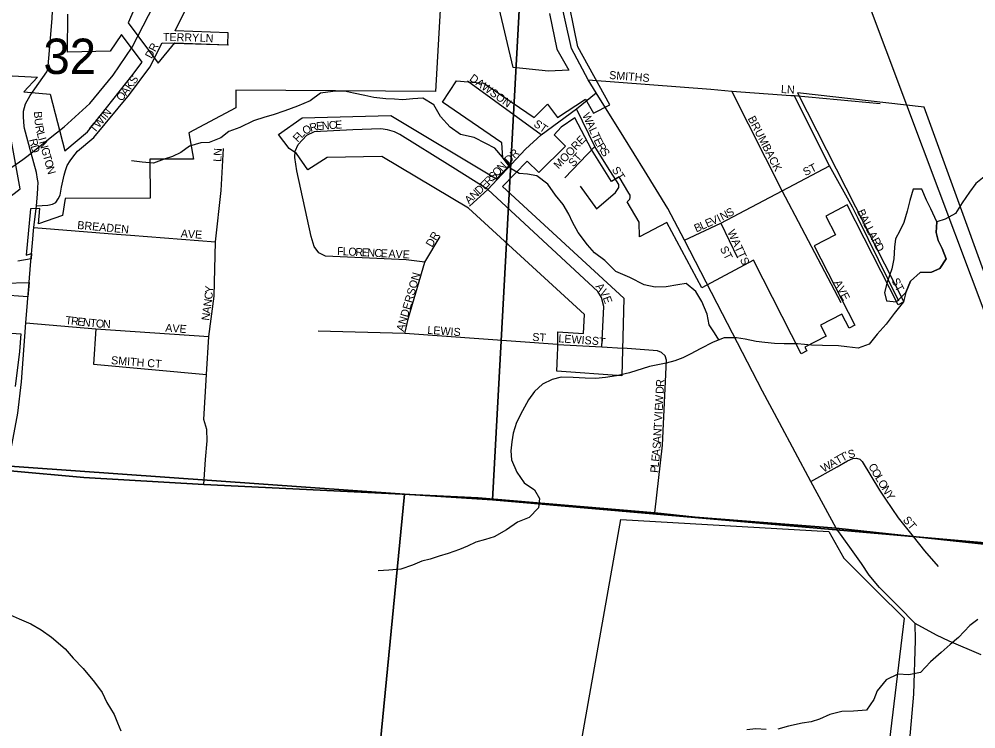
# Model space of a CAD drawing. Extents: x 1715311 to 2083412, y 146837 to 553079.
# Drawn here: x 1929182 to 1935157, y 372254 to 376689 of the extents above; entities that cross this region are included whole.
import ezdxf

# ---------------------------------------------------------------- set-up
doc = ezdxf.new("R2010")
doc.units = 0
for name, color, linetype in [('GM_X_City_Street', 7, 'Continuous'), ('GM_X_City_Street_Text', 7, 'Continuous'), ('GM_X_Corporation', 7, 'Continuous'), ('GM_X_County_Road', 7, 'Continuous'), ('GM_X_Minor_Lake', 7, 'Continuous'), ('GM_X_Minor_River', 7, 'Continuous'), ('GM_X_Rail_Line', 7, 'Continuous'), ('GM_X_Section', 7, 'Continuous'), ('GM_X_Section_Text', 7, 'Continuous'), ('GM_X_State_Route', 7, 'Continuous'), ('GM_X_Township', 7, 'Continuous'), ('GM_X_Township_Road', 7, 'Continuous'), ('GM_X_Township_Subdivision', 7, 'Continuous'), ('GM_X_Township_Subdivision_Text', 7, 'Continuous')]:
    doc.layers.add(name, color=color, linetype=linetype)

msp = doc.modelspace()

# ---------------------------------------------------------------- linework, layer by layer
at = {"layer": 'GM_X_City_Street'}
for points in [[(1929289.6, 375522.6), (1929360.2, 375525.4), (1929389.3, 375532.4), (1929410.5, 375543), (1929424.6, 375565.7), (1929437.4, 375589), (1929447.3, 375638.6), (1929462.8, 375713.7), (1929470.6, 375743.4), (1929481.9, 375773.1), (1929499.6, 375803.5), (1929516.6, 375826.9), (1929545.6, 375863.7), (1929649.2, 375948.4), (1929870.5, 376217.7), (1929997.3, 376387.3), (1930076.1, 376541.1)], [(1930076.1, 376541.1), (1930489.2, 376528.3)], [(1929296.8, 375688.7), (1929289.5, 375729.2), (1929256.7, 375851.9), (1929215.6, 376005.6), (1929212.7, 376019.6), (1929208.5, 376075.8), (1929208.5, 376112.4), (1929221.7, 376160.1), (1929250.1, 376211.9), (1929279.3, 376252.9)], [(1932442.6, 375965.2), (1931981.4, 376300.1)], [(1932734.8, 376309.1), (1933502.7, 376251.6), (1933632.3, 376239.2), (1934001.9, 376211.9)], [(1931994.4, 375519.3), (1932109.6, 375624.2), (1932345, 375875.1), (1932442.6, 375965.2), (1932662.8, 376128.3), (1932785.4, 376227.9)], [(1934315.7, 374914.9), (1933948, 375616.1), (1933632.3, 376239.2)], [(1934001.9, 376211.9), (1934022.8, 376210.4), (1934558.7, 376160.3)], [(1934421.8, 375443), (1934386.7, 375514.1), (1934243.1, 375772.5), (1934022.8, 376210.4)], [(1932822, 374640.1), (1932832.7, 374893.7), (1932818.1, 374949.8), (1932795.2, 374987.2), (1932109.6, 375624.2), (1931873.5, 375772), (1931560.4, 375966.8), (1931526.5, 375985.3), (1931481.8, 375996.1), (1931440.1, 376002.3), (1931265.8, 375996.1), (1931023.7, 375983.8), (1930977.4, 375960.6), (1930923.9, 375905.3)], [(1933337, 375307.7), (1933565, 375414.6), (1933948, 375616.1), (1934243.1, 375772.5)], [(1929299.1, 375635.1), (1929300.8, 375666.9), (1929296.8, 375688.7)], [(1934676.7, 374925.7), (1934421.8, 375443)], [(1929266.6, 375313.2), (1929271.1, 375366.9)], [(1933565, 375414.6), (1933667.6, 375196.1)], [(1932544, 374656.2), (1932822, 374640.1), (1932951.2, 374632.6)]]:
    msp.add_lwpolyline(points, dxfattribs=at)
at = {"layer": 'GM_X_Corporation'}
for points in [[(1936214.9, 372337.8), (1934834.2, 376139.2), (1934042.4, 376228.4), (1934706.1, 374922.7), (1934670.8, 374903.9), (1934353, 375527.7), (1934220.5, 375457.3), (1934279.7, 375341.1), (1934147.8, 375271.6), (1934400.6, 374775.4), (1934365.3, 374756.6), (1934319.9, 374845.7), (1934187.4, 374775.3), (1934221.5, 374708.5), (1934089, 374638), (1934100.4, 374615.7), (1934065.1, 374597), (1933767.3, 375181.4), (1933445.1, 375010.1), (1933226.3, 375418.5), (1933055.9, 375327.2), (1933054.7, 375420.6), (1932979.2, 375546.5), (1932996, 375564.4), (1932997.9, 375573.5), (1932998.4, 375581.2), (1932997, 375587.6), (1932994, 375594.8), (1932990, 375601.6), (1932928.4, 375703.9), (1932881.4, 375674.3), (1932757.3, 375874.9), (1932653.2, 376071.2), (1932567.9, 376014), (1932522.4, 375966.5), (1932593.6, 375894.9), (1932427.1, 375731.1), (1932355.3, 375801.4), (1932199.7, 375643.4), (1932959.2, 374945.2), (1932946.8, 374459.4), (1932540.4, 374488), (1932543.3, 374586.9), (1932545.8, 374636.2), (1932546.3, 374734.5), (1932706.8, 374725.2), (1932712.2, 374842.4), (1931987.8, 375507.6), (1931446.8, 375830.9), (1931105.2, 375823.8), (1930985.2, 375746.1), (1930913.5, 375848.7), (1930868.8, 375880.7), (1930801, 375968.3), (1930949.1, 376071.1), (1931502.4, 376085.7), (1932162.5, 375691.4), (1932246.1, 375777.1), (1932202.9, 375821.4), (1932196, 375915.3), (1931825.8, 376169.5), (1931912.6, 376301.9), (1932083.6, 376288.6), (1932398.9, 376073.8), (1932482.6, 376156.7), (1932544.2, 376072.8), (1932719.2, 376187.6), (1932768.6, 376101.2), (1932870.9, 376153.5), (1932670.3, 376516.1), (1932439.1, 377654.7)], [(1930094.3, 377191.6), (1929862.3, 376665.7), (1930049.9, 376412.6), (1930154.7, 376540.1), (1930485, 376528.6), (1930487.6, 376603.6), (1930157.3, 376615), (1930453, 377221.9)], [(1931823.4, 376968.1), (1931782.7, 376237.3), (1930535.1, 376245.3), (1930535.1, 376134.3), (1930241, 375978), (1930269.9, 375814.5), (1929998.9, 375813.7), (1929999.6, 375569.7), (1929469.7, 375568.2), (1929452.8, 375461.6), (1929303.4, 375410.2), (1929311.8, 375505.8), (1929252, 375503.9), (1929225, 375213.5), (1929259.2, 375224.1), (1929256.3, 375189.9), (1929174, 375176)], [(1932494.6, 376724.1), (1932540.1, 376500.4), (1932614.9, 376369.7), (1932488.6, 376362.6), (1932266.9, 376385.7), (1932135.2, 376945)], [(1927558.8, 376417.6), (1929297.4, 376326.5), (1929211.5, 376234.3), (1929375.2, 376218.8), (1929466.4, 375864.8), (1929608.5, 375985.3), (1929886, 376333.7), (1929950.2, 376419.7), (1929821.5, 376593.3), (1929749.9, 376487.3), (1929482.9, 376483), (1929486.3, 376720.4)], [(1928437.1, 375046), (1929187.5, 375627.6), (1929129.3, 375947.9)], [(1929085.2, 375038), (1929244, 375042.7), (1929236.7, 374954.2), (1929060.4, 374966.3)], [(1928992.9, 374736.2), (1929192, 374722.3), (1929184.8, 374612.5), (1929156.6, 374393.4)], [(1932627.8, 371801.6), (1932940.7, 373562.5), (1934238.3, 373487), (1934331.9, 373320), (1934538.6, 373114.3), (1934708.4, 372945.2), (1934539.1, 371529.5)]]:
    msp.add_lwpolyline(points, dxfattribs=at)
at = {"layer": 'GM_X_County_Road'}
msp.add_lwpolyline([(1934840.3, 365923), (1934840.3, 365923), (1934895.7, 366213.4), (1934955.5, 366767), (1935067.3, 367543.2), (1935088.4, 367796.8), (1935095.4, 367863.8), (1935109.5, 368025.8), (1935123.6, 368825.4), (1935109.8, 369485.3), (1935106.9, 369589.8), (1935083.7, 369752.3), (1935008.2, 370103.6), (1934915.4, 370396.7), (1934845.7, 370598.2), (1934804.1, 370738.9), (1934750.3, 370985.5), (1934692.5, 371435.5), (1934684.9, 371550.8), (1934692.5, 371687.7), (1934739.2, 372114.7), (1934769.8, 372470.5), (1934780.7, 372807.5), (1934778.4, 372912.2)], dxfattribs=at)
at = {"layer": 'GM_X_Minor_Lake'}
for points in [[(1934914, 375421.9), (1934876.3, 375502.2), (1934848.5, 375558.3), (1934818.7, 375626.5), (1934764.8, 375626.7), (1934744.6, 375554.7), (1934728.4, 375488.6), (1934706.1, 375418.6), (1934682, 375366.7), (1934655.8, 375314.7), (1934649.6, 375262.6), (1934645.4, 375190.6), (1934631.2, 375128.6), (1934602.9, 375044.5), (1934586.7, 374980.5), (1934598.5, 374928.4), (1934660.5, 374922.2), (1934720.6, 374980.1)], [(1934720.6, 374980.1), (1934748.8, 375052.1), (1934809, 375105.9), (1934880.9, 375107.7), (1934931, 375129.5), (1934971.1, 375191.5), (1934947.4, 375255.6), (1934921.6, 375305.8), (1934909.7, 375355.9), (1934914, 375421.9)]]:
    msp.add_lwpolyline(points, dxfattribs=at)
at = {"layer": 'GM_X_Minor_River'}
for points in [[(1932994.9, 375073.1), (1932908.9, 375111.6), (1932839.4, 375180.2), (1932775.8, 375228.7), (1932732.2, 375279), (1932672.8, 375355.5), (1932637.3, 375419.8), (1932615.7, 375470.1), (1932580.1, 375530.4), (1932532.5, 375588.8), (1932483.1, 375657.2), (1932415.5, 375709.7), (1932357.6, 375720.1), (1932305.7, 375724.5), (1932253.9, 375752.8), (1932200.5, 375825.3), (1932152.9, 375881.7), (1932097.2, 375912.1), (1932023.5, 375948.6), (1931937.7, 375967.2), (1931874.1, 376013.7), (1931812.6, 376080.2), (1931771.2, 376152.5), (1931703.5, 376195), (1931641.6, 376191.5), (1931577.6, 376183.9), (1931525.7, 376188.2), (1931471.7, 376190.6), (1931397.9, 376199.1), (1931340, 376211.5), (1931270.2, 376226), (1931214.3, 376238.4), (1931140.4, 376236.9), (1931064.4, 376225.4), (1931000.1, 376177.7), (1930920, 376144.2), (1930841.9, 376114.7), (1930767.8, 376091.2), (1930715.7, 376075.5), (1930645.6, 376052), (1930559.4, 376010.5), (1930491.4, 375986.9), (1930441.1, 375947.2), (1930369, 375917.6), (1930317.1, 375916), (1930245, 375894.4), (1930190.8, 375854.7), (1930140.7, 375831), (1930088.6, 375813.4), (1930020.5, 375787.8), (1929950.6, 375794.3), (1929882.7, 375802.7)], [(1935208.7, 375703.3), (1935156.6, 375661.4), (1935116.4, 375607.5), (1935072.2, 375541.5), (1935030, 375473.6), (1934966, 375437.8), (1934914, 375421.9), (1934909.7, 375355.9), (1934921.6, 375305.8), (1934947.4, 375255.6), (1934971.1, 375191.5), (1934931, 375129.5), (1934880.9, 375107.7), (1934809, 375105.9), (1934748.8, 375052.1), (1934720.6, 374980.1), (1934704.4, 374922.1), (1934646.2, 374848.2), (1934596, 374782.3), (1934539.9, 374720.4), (1934489.7, 374658.5), (1934421.7, 374632.7), (1934351.8, 374640.9), (1934299.8, 374647.1), (1934199.9, 374649.5), (1934130, 374651.7), (1934042.1, 374660), (1933960.2, 374660.3), (1933900.2, 374662.5), (1933838.3, 374668.7), (1933784.4, 374674.9), (1933716.5, 374689.1), (1933662.6, 374697.3), (1933584.6, 374697.6), (1933516.6, 374669.8), (1933434.5, 374628), (1933376.5, 374596.2), (1933326.4, 374572.3), (1933276.4, 374552.5), (1933222.4, 374538.6), (1933118.4, 374519), (1932994.1, 374478.4)], [(1933551.9, 374684.2), (1933524.8, 374727.8), (1933491, 374778), (1933479.2, 374844.1), (1933445.5, 374924.3), (1933407.8, 374986.5), (1933348, 375036.8), (1933296, 375029), (1933222, 375015.2), (1933154.1, 375013.4), (1933086.2, 375027.7), (1932994.9, 375073.1)], [(1932994.1, 374478.4), (1932912.5, 374458.8), (1932844.5, 374449.2), (1932784.5, 374443.6), (1932716.6, 374446.1), (1932642.7, 374448.6), (1932566.8, 374451.1), (1932510.7, 374437.5), (1932450.6, 374407.8), (1932400.3, 374362.1), (1932362, 374310.3), (1932325.6, 374240.5), (1932289.1, 374168.6), (1932266.7, 374100.7), (1932258.3, 374046.7), (1932251.9, 373990.6), (1932257.5, 373934.5), (1932291, 373858.2), (1932336.5, 373791.8), (1932400.1, 373747.3), (1932431.7, 373693.1), (1932425.3, 373635), (1932367, 373575.3), (1932294.9, 373545.8), (1932224.6, 373498.2), (1932148.4, 373452.7), (1932094.3, 373437), (1932034.3, 373419.4), (1931982.2, 373395.7), (1931932.1, 373374), (1931862, 373350.4), (1931805.9, 373332.8), (1931747.9, 373315.2), (1931697.8, 373301.5), (1931637.7, 373275.8), (1931565.6, 373252.3), (1931491.6, 373244.8), (1931423.7, 373241.2)], [(1929126.2, 372966.2), (1929181.9, 372941.8), (1929255.6, 372909.3), (1929319.3, 372872.8), (1929384.9, 372826.3), (1929468.4, 372753.7), (1929519.9, 372695.3), (1929581.4, 372630.8), (1929652.8, 372546.2), (1929700.3, 372481.8), (1929729.8, 372419.5), (1929775.3, 372343.1), (1929796.9, 372290.9), (1929816.5, 372240.7)], [(1935169.2, 372938.2), (1935119.1, 372900.3), (1935048.9, 372824.5), (1934996.8, 372780.6), (1934940.7, 372730.7), (1934874.6, 372672.9), (1934810.4, 372607), (1934738.4, 372591.2), (1934670.5, 372595.5), (1934596.4, 372559.7), (1934540.2, 372491.8), (1934520.1, 372437.8), (1934473.9, 372369.9), (1934391.9, 372364.1), (1934320, 372362.4), (1934246, 372344.6), (1934179.9, 372314.8), (1934127.9, 372297), (1934071.9, 372289.1), (1933986, 372271.4), (1933920, 372251.6)], [(1933848, 372249.8), (1933782.1, 372254.1), (1933726.1, 372248.3)]]:
    msp.add_lwpolyline(points, dxfattribs=at)
at = {"layer": 'GM_X_Rail_Line'}
msp.add_lwpolyline([(1938690.8, 365514.6), (1938582.1, 365878.3), (1938322.7, 366575), (1937940.6, 367593.6), (1937212.9, 369527.6), (1936367.6, 371778.4), (1935832.6, 373203.1), (1935532.7, 374002.5), (1934726.1, 376150.5), (1933822.3, 378557.6), (1933243.5, 380098.4), (1933190.5, 380215.7), (1933147, 380301.7), (1933102.7, 380385.1), (1933064.5, 380457.2), (1933017.6, 380530.2), (1932890.3, 380711.6), (1932780, 380850.5), (1932651.5, 380992.4)], dxfattribs=at)
at = {"layer": 'GM_X_Section'}
for points in [[(1926912.1, 379353.7), (1932428, 379000.4), (1932139, 373684.4), (1931589, 373719.5), (1926539.2, 374077.9)], [(1932428, 379000.4), (1937617.3, 378541.2), (1937153.6, 373248.9), (1936715.6, 373285.2), (1932139, 373684.4)], [(1926539.2, 374077.9), (1931589, 373719.5), (1931067.9, 368370), (1925814.1, 368746.8), (1926287.1, 374098.4)], [(1932139, 373684.4), (1936715.6, 373285.2), (1936391.8, 367922.8), (1933009.6, 368248), (1931067.9, 368370), (1931589, 373719.5)]]:
    msp.add_lwpolyline(points, close=True, dxfattribs=at)
at = {"layer": 'GM_X_State_Route'}
for points in [[(1929386.7, 375955), (1929462.3, 376014.9), (1929624.3, 376160.5), (1929768.2, 376338.3), (1929887.8, 376513.4), (1930058.5, 376845.6), (1930374.8, 377451.7), (1930469.8, 377580.7), (1930609.2, 377759.7), (1930708, 377846.9)], [(1932592.3, 376682.6), (1932414.5, 377482.9), (1932413.4, 377487.8)], [(1932957.8, 375951.3), (1932785.4, 376227.9), (1932734.8, 376309.1), (1932631.8, 376504.8), (1932592.3, 376682.6)], [(1929220.6, 375823.4), (1929256.7, 375851.9), (1929386.7, 375955)], [(1933574.5, 374848.1), (1933337, 375307.7), (1933233.5, 375504.2), (1933088.4, 375741.8), (1932957.8, 375951.3)], [(1929004, 375670.9), (1929204.6, 375810.7), (1929220.6, 375823.4)], [(1933930.8, 374165.7), (1933824.5, 374364.1), (1933574.5, 374848.1)], [(1934673.8, 373017.7), (1934554.8, 373137.9), (1934490.4, 373214.9), (1934443.3, 373287.3), (1934380.1, 373374.7), (1934283.5, 373507.2), (1934126.8, 373799.8), (1933930.8, 374165.7)], [(1935190.3, 372717), (1934990.3, 372801.5), (1934910.5, 372839.6), (1934778.4, 372912.2), (1934673.8, 373017.7)]]:
    msp.add_lwpolyline(points, dxfattribs=at)
at = {"layer": 'GM_X_Township'}
for points in [[(1920583.1, 374570.2), (1923184.5, 374353.4), (1923645, 374303.8), (1923790.4, 374289.2), (1924848.7, 374202.5), (1925971.3, 374118.1), (1926560.2, 374072.6), (1926868.1, 374061.2), (1927435.6, 374005.6), (1928004.1, 373946.8), (1928212.6, 373930.4), (1929126.9, 373865.9), (1929585.2, 373824.4), (1930335.7, 373779.9), (1931574, 373720.8), (1932048.3, 373697.2), (1933152.9, 373602.8), (1933404.2, 373577.5), (1934283.5, 373507.2), (1934765.2, 373455), (1936669.2, 373248.8), (1937122, 373218.3), (1942174.3, 372734.4)], [(1942174.3, 372734.4), (1937122, 373218.3), (1936669.2, 373248.8), (1934765.2, 373455), (1934283.5, 373507.2), (1933404.2, 373577.5), (1933152.9, 373602.8), (1932048.3, 373697.2), (1931574, 373720.8), (1930335.7, 373779.9), (1929585.2, 373824.4), (1929126.9, 373865.9), (1928212.6, 373930.4), (1928004.1, 373946.8), (1927435.6, 374005.6), (1926868.1, 374061.2), (1926560.2, 374072.6), (1925971.3, 374118.1), (1924848.7, 374202.5), (1923790.4, 374289.2), (1923645, 374303.8), (1923184.5, 374353.4), (1920583.1, 374570.2)]]:
    msp.add_lwpolyline(points, dxfattribs=at)
at = {"layer": 'GM_X_Township_Road'}
for points in [[(1929279.3, 376252.9), (1929354.8, 376359.2), (1929361.2, 376374.5), (1929368.6, 376466.8), (1929387.2, 376694.4), (1929390.8, 376739.1), (1929393, 376765.8)], [(1929271.1, 375366.9), (1929272.7, 375385.8), (1929289.6, 375522.6), (1929297, 375594.4), (1929299.1, 375635.1)], [(1929253.1, 375151.9), (1929266.6, 375313.2)], [(1929244.2, 375044.3), (1929253.1, 375151.9)], [(1929126.9, 373865.9), (1929119.8, 373936.6), (1929172.8, 374225.4), (1929197.5, 374422), (1929223.1, 374791.4), (1929244.2, 375044.3)], [(1929155.2, 373863.4), (1929585.2, 373824.4), (1930335.7, 373779.9), (1931574.1, 373720.8), (1932048.3, 373697.2), (1933153, 373602.8), (1933404.2, 373577.5), (1934283.5, 373507.2)]]:
    msp.add_lwpolyline(points, dxfattribs=at)
at = {"layer": 'GM_X_Township_Subdivision'}
for points in [[(1932856.8, 375765.5), (1932777.3, 375892.3), (1932662.8, 376128.3)], [(1931716.2, 375169), (1931599, 375184.5), (1931096.2, 375207.6), (1931054.5, 375227.7), (1931023.7, 375267.8), (1931005.2, 375331.1), (1930915.7, 375741.5), (1930903.4, 375823.3), (1930906.4, 375863.4), (1930923.9, 375905.3)], [(1930335.3, 374187.5), (1930351.5, 374468.1), (1930367.4, 374704.8), (1930398.9, 374958.5), (1930408.8, 375297.1), (1930443.1, 375618.1), (1930458.9, 375880.2)], [(1932590, 375696.3), (1932777.3, 375892.3)], [(1932787.7, 375503.8), (1932907.3, 375606.1), (1932928.1, 375637.3), (1932926.4, 375654.7), (1932856.8, 375765.5)], [(1932686.2, 375643.9), (1932787.7, 375503.8)], [(1929272.7, 375385.8), (1929789.1, 375345.8)], [(1929789.1, 375345.8), (1929877, 375339), (1930408.8, 375297.1)], [(1931590, 374723.2), (1931612.9, 374823), (1931716.2, 375169), (1931811.9, 375329.5)], [(1929223.1, 374791.4), (1929661, 374752.5), (1930367.4, 374704.8)], [(1929661, 374752.5), (1929646.9, 374531.7), (1930351.5, 374468.1)], [(1932544, 374656.2), (1931590, 374723.2), (1931050.1, 374738.3)], [(1933153, 373602.8), (1933199.1, 374027), (1933223.9, 374557.3), (1933216.3, 374584.1), (1933193.3, 374605.1), (1933169.4, 374616.6), (1932951.2, 374632.6)], [(1930335.7, 373779.9), (1930345, 373936), (1930355.3, 374053), (1930354.2, 374123.8), (1930335.3, 374187.5)], [(1934126.8, 373799.8), (1934290.5, 373890.8), (1934356, 373927.6), (1934389.3, 373943.7), (1934411.1, 373944.9), (1934431.8, 373939.1), (1934447.9, 373925.3), (1934554.8, 373746), (1934593.2, 373688.5)], [(1934593.2, 373688.5), (1934670.8, 373572.4), (1934765.2, 373455), (1934836.3, 373366.6), (1934922.4, 373267.8)]]:
    msp.add_lwpolyline(points, dxfattribs=at)

# ---------------------------------------------------------------- texts
at = {"layer": 'GM_X_City_Street_Text'}
for s, rotation, p in [('TERRY', 358.75526, (1930079.6, 376552.6)), ('LN', 356.97755, (1930308.7, 376548.2)), ('DR', 62.10863, (1930009.5, 376437.8)), ('S', 54.45607, (1929904.5, 376278.6)), ('DAWSON', 324.24623, (1931990.1, 376309.1)), ('SMITHS', 355.51347, (1932865.4, 376315.2)), ('A', 52.2467, (1929850.7, 376206.3)), ('K', 54.38267, (1929878.8, 376242.8)), ('LN', 356.98902, (1933938.7, 376227.2)), ('O', 50.32313, (1929821.4, 376171.1)), ('B', 271.55473, (1929274.9, 376111.9)), ('TWIN', 50.60067, (1929654.2, 375973)), ('BRUMBACK', 297.21577, (1933731, 376068.1)), ('U', 276.54962, (1929276.3, 376067.5)), ('R', 281.60116, (1929282.1, 376019.1)), ('O', 28.85292, (1930967.3, 375964.1)), ('R', 14.68422, (1931002.8, 375984.1)), ('E', 5.83023, (1931039.1, 375993.8)), ('N', 3.89405, (1931073.7, 375997.3)), ('C', 3.91283, (1931117.6, 376000.3)), ('E', 3.91041, (1931157.1, 376003)), ('ST', 325.30922, (1932390.4, 376023.1)), ('L', 285.56074, (1929290.9, 375976.6)), ('F', 45.90815, (1930921.5, 375915.9)), ('L', 45.91673, (1930945.9, 375941.2)), ('R', 282.71061, (1929244, 375935.8)), ('D', 285.54751, (1929253.4, 375894.6)), ('I', 285.39311, (1929300.3, 375942.7)), ('N', 285.40083, (1929306.2, 375921.5)), ('G', 285.40083, (1929317.9, 375879.1)), ('T', 285.40852, (1929329.6, 375836.7)), ('DR', 45, (1932242, 375780.1)), ('O', 285.39892, (1929338.9, 375802.7)), ('N', 46.90142, (1932197.5, 375733.5)), ('ST', 26.56505, (1934092.4, 375707)), ('N', 285.37205, (1929350.6, 375760.3)), ('S', 46.92716, (1932143.4, 375675.6)), ('O', 46.90142, (1932167.5, 375701.3)), ('E', 44.97585, (1932090.1, 375620.5)), ('R', 46.81842, (1932116.2, 375646.7)), ('N', 42.65858, (1932023.8, 375559.4)), ('D', 42.70634, (1932056.2, 375589.2)), ('A', 42.65008, (1931991.5, 375529.5)), ('N', 27.46185, (1933574.5, 375428.8)), ('S', 27.62687, (1933613.7, 375449.1)), ('B', 294.57664, (1934413.3, 375486.7)), ('B', 23.84907, (1933410.8, 375355.2)), ('L', 23.82653, (1933447.1, 375371.2)), ('E', 23.83753, (1933479.3, 375385.5)), ('V', 24.12286, (1933511.7, 375399.8)), ('I', 25.96571, (1933553.5, 375418.5)), ('A', 296.76642, (1934430.6, 375448.8)), ('L', 297.45929, (1934450.8, 375409)), ('WATTS', 294.44321, (1933603.6, 375359.3)), ('L', 297.47568, (1934467, 375377.7)), ('A', 297.46435, (1934483.2, 375346.5)), ('R', 297.46668, (1934503.5, 375307.4)), ('ST', 296.56506, (1933557.3, 375255.2)), ('D', 297.4815, (1934521.8, 375272.3)), ('ST', 296.56506, (1934628.6, 375056)), ('A', 305.19974, (1932779.8, 375017.7)), ('V', 300.6827, (1932804.6, 374982.7)), ('AVE', 297.47059, (1934267.8, 375043)), ('E', 290.43133, (1932826.1, 374947)), ('LEWIS', 355.9166, (1932548.5, 374669.6)), ('ST', 352.39486, (1932755.9, 374656.3))]:
    msp.add_text(s, height=50, rotation=rotation, dxfattribs=at).set_placement(p)
at = {"layer": 'GM_X_Section_Text'}
msp.add_text('32', height=221, rotation=0.00001, dxfattribs=at).set_placement((1929333.6, 376345.7))
at = {"layer": 'GM_X_Township_Subdivision_Text'}
for s, rotation, p in [('W', 294.49684, (1932697.2, 376089.7)), ('A', 294.51057, (1932720.9, 376037.6)), ('MOORE', 46.63889, (1932550.6, 375748.8)), ('L', 294.48693, (1932739.2, 375997.6)), ('T', 294.50262, (1932753.8, 375965.6)), ('E', 295.84873, (1932768.9, 375932.4)), ('R', 302.10199, (1932787.1, 375895.5)), ('LN', 86.98901, (1930444.1, 375795.9)), ('ST', 47.4879, (1932643, 375761.4)), ('S', 303.65897, (1932809, 375860.7)), ('ST', 302.74312, (1932881.3, 375747.7)), ('BREADEN', 354.80527, (1929543.5, 375378)), ('AVE', 356.0574, (1930190.1, 375325.2)), ('DR', 59.5322, (1931760.9, 375259)), ('F', 357.10211, (1931166.7, 375215.2)), ('L', 357.10211, (1931201.9, 375213.4)), ('O', 357.11061, (1931237, 375211.7)), ('R', 357.1061, (1931281, 375209.4)), ('E', 357.10211, (1931320.5, 375207.4)), ('N', 357.11061, (1931355.7, 375205.7)), ('C', 357.1061, (1931399.6, 375203.4)), ('E', 357.10211, (1931439.2, 375201.4)), ('A', 357.09175, (1931487.5, 375199)), ('V', 357.11061, (1931531.5, 375196.8)), ('E', 358.13503, (1931576.4, 375194.5)), ('ANDERSON', 73.95144, (1931584, 374733.2)), ('Y', 86.19817, (1930392.1, 374976.3)), ('N', 82.12951, (1930381.4, 374889.5)), ('C', 83.73885, (1930387.6, 374934.6)), ('A', 82.12951, (1930375.3, 374845.9)), ('T', 353.53913, (1929468.9, 374784)), ('R', 353.54741, (1929503.9, 374780)), ('E', 353.54955, (1929543.2, 374775.6)), ('N', 353.53913, (1929578.2, 374771.6)), ('N', 82.15116, (1930369.3, 374802.3)), ('T', 354.04543, (1929622.4, 374766.6)), ('O', 356.61488, (1929659.9, 374762.7)), ('N', 357.40325, (1929704.5, 374760.1)), ('AVE', 356.05688, (1930093.3, 374735.6)), ('LEWIS', 355.91143, (1931730.1, 374722.4)), ('ST', 356.42622, (1932385.6, 374678.4)), ('SMITH CT', 355.53183, (1929754.6, 374533.2)), ('R', 86.98721, (1933208.7, 374389.7)), ('D', 86.98261, (1933206.4, 374345.7)), ('E', 86.96566, (1933200.9, 374240.2)), ('W', 86.99628, (1933202.7, 374275.4)), ('I', 86.98261, (1933199.7, 374218.2)), ('T', 86.99866, (1933194.8, 374126)), ('V', 87.00443, (1933197.4, 374174.3)), ('N', 86.99807, (1933192.5, 374082)), ('S', 85.21423, (1933187, 374001.3)), ('A', 86.73897, (1933190, 374037.8)), ('A', 84.30897, (1933182.5, 373956.7)), ('T', 28.6061, (1934324.5, 373921.9)), ("'", 23.30386, (1934354.3, 373938.2)), ('S', 13.56586, (1934364.3, 373942.7)), ('E', 84.30843, (1933179.1, 373921.6)), ('W', 29.73237, (1934206.3, 373854.3)), ('A', 29.71718, (1934255.9, 373882.7)), ('T', 29.73414, (1934294.2, 373904.5)), ('P', 84.30843, (1933172.1, 373851.6)), ('L', 84.30843, (1933175.6, 373886.6)), ('C', 300.4557, (1934483.2, 373895)), ('O', 300.43895, (1934503.2, 373860.8)), ('L', 300.45085, (1934525.5, 373822.9)), ('O', 300.45463, (1934543.4, 373792.5)), ('N', 300.45779, (1934565.7, 373754.6)), ('Y', 303.19905, (1934589.4, 373714.5)), ('ST', 309.79841, (1934697.9, 373557.4))]:
    msp.add_text(s, height=50, rotation=rotation, dxfattribs=at).set_placement(p)

doc.saveas('drawing.dxf')
